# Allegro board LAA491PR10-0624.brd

Outline 230.4 x 191.1 mm; copper layers: TOP, GND1, IN1, VCC, IN2, IN3, GND2, BOTTOM. Coordinates in mm from the lower left corner of the outline.
Outline path: 0,56.85 10.3,56.85 arc(10.8,57.35) 10.3,57.85 10.3,69.35 arc(10.8,69.85) 10.3,70.35 0.8,70.35 0.8,74.66 13.2,74.66 arc(13.7,75.16) 13.2,75.66 13.2,89.94 arc(13.7,90.44) 13.2,90.94 0.6,90.94 0.6,95.91 1.69,95.91 arc(2.4,96.2) 2.69,96.91 2.69,99.5 4.3,99.5 arc(5.3,100.5) 4.3,101.5 4.3,114.5 arc(5.3,115.5) 4.3,116.5 2.69,116.5 2.69,120.4 23.65,120.4 arc(24.11,120.51) 24.46,120.83 arc(27.53,122.04) 29.86,119.7 arc(30.21,119.13) 30.84,118.9 37,118.9 arc(37.71,119.19) 38,119.9 38,120.4 48,120.4 arc(64.11,124.09) 77.01,134.43 arc(77.49,134.76) 78.07,134.77 arc(78.68,134.78) 79.17,135.14 arc(81.4,138.65) 83.23,142.37 arc(83.29,142.98) 82.98,143.51 arc(82.68,144.01) 82.71,144.59 arc(84.42,150.9) 85,157.4 85,159.8 89.93,159.8 89.93,153.52 arc(90.37,152.46) 91.43,152.02 118.73,152.02 arc(119.79,152.46) 120.23,153.52 120.23,159.8 124.5,159.8 arc(125.21,160.09) 125.5,160.8 125.5,190.1 133.8,190.1 arc(134.51,190.39) 134.8,191.1 160.3,191.1 arc(160.59,190.39) 161.3,190.1 198.4,190.1 198.4,182.1 arc(198.69,181.39) 199.4,181.1 202.2,181.1 202.2,180.6 arc(202.49,179.89) 203.2,179.6 225.2,179.6 arc(225.91,179.89) 226.2,180.6 226.2,181.1 230.4,181.1 230.4,0 165.4,0 165.4,7.48 arc(165.11,8.19) 164.4,8.48 89.4,8.48 89.4,11.48 arc(89.11,12.19) 88.4,12.48 62.4,12.48 arc(61.69,12.19) 61.4,11.48 61.4,8.98 56.4,8.98 arc(56.05,8.83) 55.9,8.48 49.9,8.48 arc(49.75,8.83) 49.4,8.98 47.4,8.98 arc(47.05,8.83) 46.9,8.48 40.9,8.48 arc(40.75,8.83) 40.4,8.98 38.4,8.98 arc(38.05,8.83) 37.9,8.48 31.9,8.48 arc(31.75,8.83) 31.4,8.98 27.8,8.98 arc(27.45,8.83) 27.3,8.48 26.84,5.22 arc(26.8,4.88) 26.77,4.55 arc(21.88,0) 17,4.57 arc(16.68,5.23) 16,5.5 0,5.5 0,8.92 12.66,8.92 arc(13.16,9.42) 12.66,9.92 12.66,15.75 arc(13.16,16.25) 12.66,16.75 0,16.75 0,21.6 7.47,21.6 arc(7.97,22.1) 7.47,22.6 7.47,34.2 arc(7.97,34.7) 7.47,35.2 0.8,35.2 0.8,39.25 10.3,39.25 arc(10.8,39.75) 10.3,40.25 10.3,51.75 arc(10.8,52.25) 10.3,52.75 0,52.75 0,56.85

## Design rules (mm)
net group CLK_: nets CLK_CPU_ITP CLK_CPU_ITP#
net group CSI: nets CSIN CSIP
net group DIFFPAIR2: nets I2C1_SCL_TCH_PAD I2C1_SDA_TCH_PAD
net group DIFFPAIR3: nets CSCL CSDA
net group DIFFPAIR5: nets EC_SMB_CK2 EC_SMB_DA2
net group DIFFPAIR9: nets CPU_EDP_AUX#_C CPU_EDP_AUX_C
net group DIFFPAIR13: nets PCSCL PCSDA
net group DIFFPAIR14: nets CRT_CLK_1 CRT_DATA_1
net group DIFFPAIR16: nets ISPSCL_R ISPSDA_R
net group DIFFPAIR17: nets DDI1_LANE_N0_C DDI1_LANE_P0_C
net group DIFFPAIR18: nets DDI1_LANE_N1_C DDI1_LANE_P1_C
net group DIFFPAIR19: nets CRT_CLK CRT_DATA
net group DIFFPAIR21: nets MDO2+ MDO2-
net group EDID_CLK: nets EDID_CLK EDID_DATA
net group MIIC_SCL: nets MIIC_SCL MIIC_SDA
net group PCIE_PRX_LANTX_P3_C: nets PCIE_PRX_LANTX_N3_C PCIE_PRX_LANTX_P3_C
net group PECI-SINGLE: nets PECI_EC PECI_KB9012
net group SENSE: nets VCCSENSE VSSSENSE
net group SMB-15: nets SML1_SMBCLK SML1_SMBDATA
net group VCIN0_PH: nets ECAGND VCIN0_PH
net group WCKA0_0: nets WCKA0_0 WCKA0B_0
net group WCKA0_1: nets WCKA0_1 WCKA0B_1
net group WCKA1_0: nets WCKA1_0 WCKA1B_0
net group WCKA1_1: nets WCKA1_1 WCKA1B_1
net group WCKB0_0: nets WCKB0_0 WCKB0B_0
net group WCKB0_1: nets WCKB0_1 WCKB0B_1
net group WCKB1_0: nets WCKB1_0 WCKB1B_0
net group WCKB1_1: nets WCKB1_1 WCKB1B_1
net group 12: nets PCH_OPI_COMP PCH_PCIE_RCOMP SATA_IREF
net group ASYNC: nets DDR3_DRAMRST# DDR3_DRAMRST#_CPU H_PROCHOT# H_PROCHOT#_R H_VCCST_PWRGD_XDP XDP_OBS0_R XDP_OBS1_R
net group AUDIO: nets PCH_AZ_BITCLK PCH_AZ_CODEC_BITCLK PCH_AZ_CODEC_RST# PCH_AZ_CODEC_SDIN0 PCH_AZ_CODEC_SDOUT PCH_AZ_CODEC_SYNC PCH_AZ_RST# PCH_AZ_SDOUT PCH_AZ_SYNC
net group CLK: nets SUSCLK
net group CLK-SINGLE: nets CLK_PCI_LPC
net group CR_LOW: nets DSWODVREN INTRUDER# PCH_DPWROK PCH_INTVRMEN PCH_RSMRST#_R SYS_PWROK SYS_PWROK_R SYS_RESET#
net group DDRA-ADD: nets DDR_A_BS0 DDR_A_BS1 DDR_A_BS2 DDR_A_CAS# DDR_A_MA0 DDR_A_MA1 DDR_A_MA2 DDR_A_MA3 DDR_A_MA4 DDR_A_MA5 DDR_A_MA6 DDR_A_MA7 DDR_A_MA8 DDR_A_MA9 DDR_A_MA10 DDR_A_MA11 DDR_A_MA12 DDR_A_MA13 DDR_A_MA14 DDR_A_MA15 DDR_A_RAS# DDR_A_WE#
net group DDRA-CTL: nets DDR_CKE0_DIMMA DDR_CKE1_DIMMA DDR_CS0_DIMMA# DDR_CS1_DIMMA# M_ODT0 M_ODT1
net group DDRA-D0: nets DDR_A_D0 DDR_A_D1 DDR_A_D2 DDR_A_D3 DDR_A_D4 DDR_A_D5 DDR_A_D6 DDR_A_D7
net group DDRA-D1: nets DDR_A_D8 DDR_A_D9 DDR_A_D10 DDR_A_D11 DDR_A_D12 DDR_A_D13 DDR_A_D14 DDR_A_D15 DDR_A_DQS1 DDR_A_DQS#1
net group DDRA-D2: nets DDR_A_D16 DDR_A_D17 DDR_A_D18 DDR_A_D19 DDR_A_D20 DDR_A_D21 DDR_A_D22 DDR_A_D23
net group DDRA-D3: nets DDR_A_D24 DDR_A_D25 DDR_A_D26 DDR_A_D27 DDR_A_D28 DDR_A_D29 DDR_A_D30 DDR_A_D31
net group DDRA-D4: nets DDR_A_D32 DDR_A_D33 DDR_A_D34 DDR_A_D35 DDR_A_D36 DDR_A_D37 DDR_A_D38 DDR_A_D39
net group DDRA-D5: nets DDR_A_D40 DDR_A_D41 DDR_A_D42 DDR_A_D43 DDR_A_D44 DDR_A_D45 DDR_A_D46 DDR_A_D47
net group DDRA-D6: nets DDR_A_D48 DDR_A_D49 DDR_A_D50 DDR_A_D51 DDR_A_D52 DDR_A_D53 DDR_A_D54 DDR_A_D55
net group DDRA-D7: nets DDR_A_D56 DDR_A_D57 DDR_A_D58 DDR_A_D59 DDR_A_D60 DDR_A_D61 DDR_A_D62 DDR_A_D63
net group DDRB-ADD: nets DDR_B_BS0 DDR_B_BS1 DDR_B_BS2 DDR_B_CAS# DDR_B_MA0 DDR_B_MA1 DDR_B_MA2 DDR_B_MA3 DDR_B_MA4 DDR_B_MA5 DDR_B_MA6 DDR_B_MA7 DDR_B_MA8 DDR_B_MA9 DDR_B_MA10 DDR_B_MA11 DDR_B_MA12 DDR_B_MA13 DDR_B_MA14 DDR_B_MA15 DDR_B_RAS# DDR_B_WE#
net group DDRB-CTL: nets DDR_CKE2_DIMMB DDR_CKE3_DIMMB DDR_CS2_DIMMB# DDR_CS3_DIMMB# M_ODT2 M_ODT3
net group DDRB-D0: nets DDR_B_D0 DDR_B_D1 DDR_B_D2 DDR_B_D3 DDR_B_D4 DDR_B_D5 DDR_B_D6 DDR_B_D7
net group DDRB-D1: nets DDR_B_D8 DDR_B_D9 DDR_B_D10 DDR_B_D11 DDR_B_D12 DDR_B_D13 DDR_B_D14 DDR_B_D15
net group DDRB-D2: nets DDR_B_D16 DDR_B_D17 DDR_B_D18 DDR_B_D19 DDR_B_D20 DDR_B_D21 DDR_B_D22 DDR_B_D23
net group DDRB-D3: nets DDR_B_D24 DDR_B_D25 DDR_B_D26 DDR_B_D27 DDR_B_D28 DDR_B_D29 DDR_B_D30 DDR_B_D31
net group DDRB-D4: nets DDR_B_D32 DDR_B_D33 DDR_B_D34 DDR_B_D35 DDR_B_D36 DDR_B_D37 DDR_B_D38 DDR_B_D39
net group DDRB-D5: nets DDR_B_D40 DDR_B_D41 DDR_B_D42 DDR_B_D43 DDR_B_D44 DDR_B_D45 DDR_B_D46 DDR_B_D47
net group DDRB-D6: nets DDR_B_D48 DDR_B_D49 DDR_B_D50 DDR_B_D51 DDR_B_D52 DDR_B_D53 DDR_B_D54 DDR_B_D55
net group DDRB-D7: nets DDR_B_D56 DDR_B_D57 DDR_B_D58 DDR_B_D59 DDR_B_D60 DDR_B_D61 DDR_B_D62 DDR_B_D63
net group DP: nets CPU_DPB_AUX CPU_DPB_AUX# CPU_DPB_AUX#_C CPU_DPB_AUX_C CPU_DPC_AUX CPU_DPC_AUX#
net group EDP: nets CPU_EDP_N0_C CPU_EDP_N1_C CPU_EDP_P0_C CPU_EDP_P1_C
net group HDA: nets AUD_HP_OUT_L_CN AUD_HP_OUT_R_CN HPOUT-L HPOUT-R MIC_IN MIC_IN_R RING2 RING2_R
net group HDMI: nets CPU_DPB_CTRLCLK CPU_DPB_CTRLDAT DDI1_LANE_N0 DDI1_LANE_N1 DDI1_LANE_P0 DDI1_LANE_P1
net group KB: nets KSI0 KSI1 KSI2 KSI3 KSI4 KSI5 KSI6 KSI7 KSO0 KSO1 KSO2 KSO3 KSO4 KSO5 KSO6 KSO7 KSO8 KSO9 KSO10 KSO11 KSO12 KSO13 KSO14 KSO15 KSO16
net group LPC: nets LPC_LAD0 LPC_LAD1 LPC_LAD2 LPC_LAD3 LPC_LFRAME#
net group LVDS: nets EDP_AUX EDP_AUX# EDP_N0 EDP_N1 EDP_P0 EDP_P1 LVDS_A0+ LVDS_A0- LVDS_A1+ LVDS_A1- LVDS_A2+ LVDS_A2- LVDS_ACLK+ LVDS_ACLK- LVDS_B0+ LVDS_B0- LVDS_B1+ LVDS_B1- LVDS_B2+ LVDS_B2- LVDS_BCLK+ LVDS_BCLK-
net group MDI: nets MDI0+ MDI0- MDI1+ MDI1- MDO0+ MDO0- MDO1+ MDO1- MDO3+ MDO3-
net group PCIE: nets PCIE_PRX_LANTX_N3 PCIE_PRX_LANTX_P3 PCIE_PTX_LANRX_N3 PCIE_PTX_LANRX_P3 PCIE_PTX_WLANRX_N4_C PCIE_PTX_WLANRX_P4_C
net group PEG: nets PEG_CTX_GRX_N0 PEG_CTX_GRX_N1 PEG_CTX_GRX_N2 PEG_CTX_GRX_N3 PEG_CTX_GRX_P0 PEG_CTX_GRX_P1 PEG_CTX_GRX_P2 PEG_CTX_GRX_P3
net group POWER: nets +0.675VS +0.675VSP +1.5VS +1.5VSP +1.5VSP_ON +1.35V +1.35VP +3V_WLAN +3VALW_PCH +3VALWP +3VLP +3VS_CAM +3VS_RT +5V_HDD +5V_PVDD +5V_USB_PWR1 +5V_USB_PWR2 +5V_USB_PWR3 +5V_USB_PWR4 +5VA +5VALWP +5VS_ODD +5VS_TOUCH +AVCC33 +DIMM1_VREF_DQ +DIMM2_VREF_DQ +DVCC33 +EC_VCCA +FAN_POWER +INV_PWR_SRC +LAN_IO +LAN_VDD +LCDVDD +MIC2-VREFO +PCH_VCCDSW +PCH_VCCDSW_R +RTCBATT +RTCVCC +SM_VREF_CA +SM_VREF_CA_DIMM +SM_VREF_DQ0 +SM_VREF_DQ0_DIMM1 +SM_VREF_DQ1 +SM_VREF_DQ1_DIMM2 +SW_LX +SWR_V12 +V18R +VCC_3IN1 +VCC_PWR_SRC +VCCIO_OUT +VCCIOA_OUT +VCHGR
net group RCOMP: nets SM_RCOMP0 SM_RCOMP1 SM_RCOMP2
net group RTC: nets PCH_RTCRST# PCH_RTCX1 PCH_RTCX2 SRTCRST#
net group SATA: nets SATA_PRX_DTX_N0 SATA_PRX_DTX_N0_C SATA_PRX_DTX_N1 SATA_PRX_DTX_P0 SATA_PRX_DTX_P0_C SATA_PRX_DTX_P1 SATA_PTX_DRX_N0 SATA_PTX_DRX_N1 SATA_PTX_DRX_P0 SATA_PTX_DRX_P1
net group SMB_10: nets DDR_XDP_SMBCLK_R1 DDR_XDP_SMBDAT_R1 SML0CLK SML0DATA
net group SPI: nets PCH_SPI_CLK PCH_SPI_CLK_R PCH_SPI_CS0# PCH_SPI_HOLD1# PCH_SPI_HOLD# PCH_SPI_MISO PCH_SPI_MISO_1 PCH_SPI_MOSI PCH_SPI_MOSI_1 PCH_SPI_WP1# PCH_SPI_WP#
net group SPK: nets INT-SPK-L+ INT-SPK-L- INT-SPK-R+ INT-SPK-R-
net group SVID: nets H_CPU_SVIDALRT# H_CPU_SVIDCLK H_CPU_SVIDDATA VR_SVID_ALRT# VR_SVID_CLK VR_SVID_DAT
net group THERMTRIP-SINGLE: nets H_THERMTRIP#
net group USB20: nets USB20_CAM_N7_R USB20_CAM_P7_R USB20_CR_N6_R USB20_CR_P6_R USB20_JUSB3_N2 USB20_JUSB3_N2_R USB20_JUSB3_P2 USB20_JUSB3_P2_R USB20_USBDB_N3_R USB20_USBDB_P3_R
net group USB30: nets USB3RN1_JUSB2 USB3RN1_JUSB2_R USB3RN2_JUSB1 USB3RN2_JUSB1_R USB3RP1_JUSB2 USB3RP1_JUSB2_R USB3RP2_JUSB1 USB3RP2_JUSB1_R USB3TN1_JUSB2_C USB3TN1_JUSB2_R USB3TN2_JUSB1_C USB3TN2_JUSB1_R USB3TP1_JUSB2_C USB3TP1_JUSB2_R USB3TP2_JUSB1_C USB3TP2_JUSB1_R
net group VRAMA1-D0: nets DDBIA1_0 DQA1_0 DQA1_1 DQA1_2 DQA1_3 DQA1_4 DQA1_5 DQA1_6 DQA1_7 EDCA1_0
net group VRAMA1-D1: nets DDBIA1_1 DQA1_8 DQA1_9 DQA1_10 DQA1_11 DQA1_12 DQA1_13 DQA1_14 DQA1_15 EDCA1_1
net group VRAMA1-D2: nets DDBIA1_2 DQA1_16 DQA1_17 DQA1_18 DQA1_19 DQA1_20 DQA1_21 DQA1_22 DQA1_23 EDCA1_2
net group VRAMA1-D3: nets DDBIA1_3 DQA1_24 DQA1_25 DQA1_26 DQA1_27 DQA1_28 DQA1_29 DQA1_30 DQA1_31 EDCA1_3
net group VRAMA-ADD: nets ADBIA0 ADBIA1 CASA0# CASA1# CKEA0 CKEA1 CSA0#_0 CSA1#_0 MAA0_0 MAA0_1 MAA0_2 MAA0_3 MAA0_4 MAA0_5 MAA0_6 MAA0_7 MAA0_8 MAA1_0 MAA1_1 MAA1_2 MAA1_3 MAA1_4 MAA1_5 MAA1_6 MAA1_7 MAA1_8 RASA0# RASA1# WEA0# WEA1#
net group VRAMA-D0: nets DDBIA0_0 DQA0_0 DQA0_1 DQA0_2 DQA0_3 DQA0_4 DQA0_5 DQA0_6 DQA0_7 EDCA0_0
net group VRAMA-D1: nets DDBIA0_1 DQA0_8 DQA0_9 DQA0_10 DQA0_11 DQA0_12 DQA0_13 DQA0_14 DQA0_15 EDCA0_1
net group VRAMA-D2: nets DDBIA0_2 DQA0_16 DQA0_17 DQA0_18 DQA0_19 DQA0_20 DQA0_21 DQA0_22 DQA0_23 EDCA0_2
net group VRAMA-D3: nets DDBIA0_3 DQA0_24 DQA0_25 DQA0_26 DQA0_27 DQA0_28 DQA0_29 DQA0_30 DQA0_31 EDCA0_3
net group VRAMB0-D0: nets DDBIB0_0 DQB0_0 DQB0_1 DQB0_2 DQB0_3 DQB0_4 DQB0_5 DQB0_6 DQB0_7 EDCB0_0
net group VRAMB0-D1: nets DDBIB0_1 DQB0_8 DQB0_9 DQB0_10 DQB0_11 DQB0_12 DQB0_13 DQB0_14 DQB0_15 EDCB0_1
net group VRAMB0-D2: nets DDBIB0_2 DQB0_16 DQB0_17 DQB0_18 DQB0_19 DQB0_20 DQB0_21 DQB0_22 DQB0_23 EDCB0_2
net group VRAMB0-D3: nets DDBIB0_3 DQB0_24 DQB0_25 DQB0_26 DQB0_27 DQB0_28 DQB0_29 DQB0_30 DQB0_31 EDCB0_3
net group VRAMB1-D0: nets DDBIB1_0 DQB1_0 DQB1_1 DQB1_2 DQB1_3 DQB1_4 DQB1_5 DQB1_6 DQB1_7 EDCB1_0
net group VRAMB1-D1: nets DDBIB1_1 DQB1_8 DQB1_9 DQB1_10 DQB1_11 DQB1_12 DQB1_13 DQB1_14 DQB1_15 EDCB1_1
net group VRAMB1-D2: nets DDBIB1_2 DQB1_16 DQB1_17 DQB1_18 DQB1_19 DQB1_20 DQB1_21 DQB1_22 DQB1_23 EDCB1_2
net group VRAMB1-D3: nets DDBIB1_3 DQB1_24 DQB1_25 DQB1_26 DQB1_27 DQB1_28 DQB1_29 DQB1_30 DQB1_31 EDCB1_3
net group VRAMB-ADD: nets ADBIB0 ADBIB1 CASB0# CASB1# CKEB0 CKEB1 CSB0#_0 CSB1#_0 DRAM_RST# DRAM_RST#_R MAB0_0 MAB0_1 MAB0_2 MAB0_3 MAB0_4 MAB0_5 MAB0_6 MAB0_7 MAB0_8 MAB1_0 MAB1_1 MAB1_2 MAB1_3 MAB1_4 MAB1_5 MAB1_6 MAB1_7 MAB1_8 RASB0# RASB1# WEB0# WEB1#
nets with their own width: min track width 0.254; nets +1.8VSP +3VALW +VGA_CORE +VGA_PCIEP CLK_BIASREF
nets with their own width: min track width 0.508; nets +1.2VSP_B+ +1.05V_PGOOD +1.05VS_APLLOPI +1.05VS_ASATA3PLL +1.05VS_AUSB3PLL +1.05VS_AXCK_DCB +1.05VS_AXCK_LCPLL +1.05VSP +1.8VGS +1.8VS +1.8VSP_ON +1.35V_MEM_GFX +1.35VGPUP +1.35VS_VGA +3VALW_PCH_GATE +3VGS +3VS +5VALW +5VS +AVDD +BIF_VDDC +CHGRTC +CPU_CORE +DPAB_VDD10 +DPAB_VDD18 +DPCD_VDD10 +DPCD_VDD18 +DPEF_VDD10 +DPEF_VDD18 +DPLL_PVDD +DPLL_VDDC +LCDVDD_CONN +MPV18 +PCIE_PVDD +PCIE_VDDR +SPV10 +SPV18 +TSVDD +VCCIO_OUT_R +VCCRTCEXT +VDD1DI +VDD_MEM15_REFDA +VDD_MEM15_REFDB +VDD_MEM15_REFSA +VDD_MEM15_REFSB +VDDC_CT +VDDCI +VDDCIP +VDDR4 +VREFG_GPU EDP_COMP GND GNDA
nets with their own width: min track width 1.27; nets +1.05VS

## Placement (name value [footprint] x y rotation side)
C1  -  [C_0402]  9.62 110.41 90 bottom
C2  -  [C_0402]  11.33 100.76 90 bottom
C3  -  [C_0402]  11.33 104.38 90 bottom
C4  -  [C_0402]  11.33 107.14 270 bottom
C5  -  [C_0402]  10.13 100.76 90 bottom
C6  -  [C_0402]  10.06 104.38 90 bottom
C7  -  [C_0402]  10.06 107.14 270 bottom
C8  -  [C_0402]  8.59 113.41 0 top
C9  -  [C_0402]  12.35 113.23 270 top
C10  -  [C_0402]  12.35 109.17 270 top
C11  -  [C_0402]  10.7 113.33 90 top
C12  -  [C_0402]  14.25 114.03 90 top
C13  -  [C_0402]  15.14 114.03 90 top
C20  -  [C_0603]  19.33 109.15 180 top
C21  -  [C_0402]  24.22 97.61 270 bottom
C22  -  [C_0402]  17.17 97.74 270 bottom
C23  -  [C_0402]  15.35 101.98 180 top
C24  -  [C_0402]  15.35 104.9 180 top
C25  -  [C_0402]  15.35 103.38 180 top
C26  -  [C_0402]  15.35 106.38 180 top
C27  -  [C_0603]  24.92 108.84 90 top
C28  -  [C_0402]  19.83 97.74 270 bottom
C29  -  [C_0402]  17.43 108.76 90 bottom
C30  -  [C_0402]  22.89 97.61 270 bottom
C31  -  [C_0402]  18.32 108.76 90 bottom
C32  -  [C_0402]  27.96 103.82 0 bottom
C33  -  [C_0402]  27.96 102.93 0 bottom
C34  -  [C_0402]  29.92 102.55 0 bottom
C35  -  [C_0402]  107.79 96.92 270 bottom
C36  -  [C_0402]  105.63 96.92 270 bottom
C37  -  [C_0402]  103.47 96.92 270 bottom
C38  -  [C_0402]  101.31 96.92 270 bottom
C39  -  [C_0603]  108.87 97.17 270 bottom
C40  -  [C_0603]  101.92 112.61 270 top
C41  -  [C_0603]  106.71 97.1 270 bottom
C42  -  [C_0603]  104.55 97.1 270 bottom
C43  -  [C_0603]  103.69 112.61 270 top
C44  -  [C_0603]  132.32 137.13 270 top
C45  -  [C_0603]  102.39 97.1 270 bottom
C46  -  [C_0402]  22.03 97.61 270 bottom
C47  -  [C_0402]  21.49 108.76 90 bottom
C48  -  [C_0402]  26.7 103.57 270 top
C49  -  [C_0402]  29.92 101.66 0 bottom
C50  -  [C_0402]  123.22 118.32 270 top
C51  -  [C_0402]  149.29 105.73 0 top
C52  -  [C_0402]  124.68 111.95 90 top
C53  -  [C_0402]  124.55 119.68 180 top
C54  -  [C_0402]  134.08 97.3 270 bottom
C55  -  [C_0402]  134.97 97.3 270 bottom
C56  -  [C_0402]  135.86 97.3 270 bottom
C57  -  [C_0402]  130.34 121.04 180 top
C58  -  [C_0402]  120.48 131.46 0 bottom
C59  -  [C_1206]  119.66 134.19 0 bottom
C60  -  [C_0603]  131.03 122.63 90 top
C61  -  [C_0402]  122.79 119.71 180 top
C62  -  [C_0402]  129.95 123.06 90 top
C63  -  [C_0402]  125.31 130.62 90 bottom
C64  -  [C_0402]  118.33 96.42 270 top
C65  -  [C_1206]  125.44 134.06 0 bottom
C66  -  [C_0603]  119.73 94.43 180 top
C67  -  [C_0402]  119.99 111.07 180 top
C68  -  [C_0402]  123.85 114.64 270 top
C69  -  [C_0402]  118.9 114.51 270 top
C70  -  [C_1206]  125.3 136.26 0 bottom
C71  -  [C_0402]  121.7 118.39 270 top
C72  -  [C_0603]  100.23 97.1 270 bottom
C73  -  [C_0402]  122.72 116.02 180 top
C74  -  [C_0603]  99.03 97.1 270 bottom
C75  -  [C_0402]  117.43 110.75 90 top
C76  -  [C_0402]  120.29 112.66 0 top
C77  -  [C_0402]  121.63 110.17 90 top
C78  -  [C_0603]  122.9 113.74 180 top
C79  -  [C_0402]  27.14 99.13 270 bottom
C80  -  [C_0402]  23.27 108.76 90 bottom
C81  -  [C_0402]  124.46 109.75 270 top
C82  -  [C_0603]  122.9 114.95 180 top
C83  -  [C_0402]  119.6 119.97 270 top
C84  -  [C_1206]  121.3 136.66 0 bottom
C85  -  [C_0402]  119.61 131.46 180 bottom
C86  -  [C_1206]  118.2 134.19 180 bottom
C87  -  [C_0402]  120.3 113.54 90 top
C88  -  [C_0402]  117.5 117.37 270 top
C89  -  [C_0402]  15.35 101.98 180 bottom
C90  -  [C_0402]  18.06 96.82 90 bottom
C91  -  [C_0402]  27.13 100.26 0 bottom
C92  -  [C_0402]  20.72 97.74 270 bottom
C93  -  [C_0603]  23.65 108.84 90 top
C94  -  [C_0402]  22.38 108.76 90 bottom
C95  -  [C_0402]  91.71 124.58 0 top
C96  -  [C_0402]  92.26 120.11 0 top
C411  -  [C_0402]  23.14 115.81 90 bottom
C2305  -  [C_0603]  99.53 29.03 0 bottom
C2306  -  [C_0603]  99.53 27.82 0 bottom
C2307  -  [C_0805]  102.58 30.96 270 bottom
C2308  -  [C_0603]  104.04 31.06 270 bottom
C2309  -  [C_0603]  95.72 26.49 270 top
C2310  -  [C_0805]  142.31 27.51 0 top
C2311  -  [C_0603]  138.33 21.79 90 top
C2312  -  [C_0603]  142.21 29.03 0 top
C2313  -  [C_0603]  139.54 21.79 90 top
C2314  -  [C_0603]  142.21 20.74 90 bottom
C2316  -  [C_0603]  93.5 27.82 180 bottom
C2318  -  [C_0603]  93.5 29.03 180 bottom
C2322  -  [C_0603]  94.52 26.49 270 top
C2323  -  [C_0603]  89.69 30.74 270 bottom
C2324  -  [C_0603]  90.9 30.74 270 bottom
C2326  -  [C_0402]  142.55 114.97 180 bottom
C2327  -  [C_0402]  159.36 85.48 90 bottom
C5212  -  [C_0402]  83.2 117.8 0 bottom
CA1  -  [C_0603]  28.54 25.92 90 bottom
CA2  -  [C_0603]  27.33 25.92 90 bottom
CA21  -  [C_0402]  34.43 20.2 0 top
CA22  -  [C_0402]  34.43 19.25 0 top
CA23  -  [C_0603]  20.41 22.11 0 bottom
CA24  -  [C_0402]  22.46 17.98 180 top
CA25  -  [C_0402]  21.1 19 0 top
CA29  -  [C_0402]  65.5 24.76 90 top
CA30  -  [C_0402]  65.5 23.9 270 top
CA31  -  [C_0402]  66.45 21.71 90 top
CA32  -  [C_0402]  66.45 20.85 270 top
CA33  -  [C_0402]  20.1 12.57 90 top
CA38  -  [C_0402]  15.98 19.12 180 top
CA39  -  [C_0402]  20.1 11.64 270 top
CA40  -  [C_0402]  17.05 19.09 0 top
CA51  -  [C_0402]  21.94 23.68 90 top
CA53  -  [C_0603]  27.91 17.47 90 bottom
CA54  -  [C_0402]  26.83 17.46 90 bottom
CA55  -  [C_0603]  31.33 13.98 0 top
CA56  -  [C_0402]  31.26 15.06 0 top
CA57  -  [C_0603]  32.1 16.9 0 top
CA58  -  [C_0402]  32.08 17.98 0 top
CA59  -  [C_0603]  32.22 23.44 0 top
CA60  -  [C_0402]  32.15 22.36 0 top
CA61  -  [C_0603]  23.75 15.96 270 top
CA62  -  [C_0603]  20.41 23.31 0 bottom
CA63  -  [C_0603]  23.75 14.56 90 bottom
CA64  -  [C_0603]  35.78 21.28 180 top
CA65  -  [C_0402]  32.15 24.52 0 top
CA67  -  [C_0603]  24.98 25.6 90 top
CA68  -  [C_0603]  26.19 25.6 90 top
CA69  -  [C_0402]  33.06 25.41 180 top
CA71  -  [C_0603]  20.86 23.76 90 top
CA74  -  [C_0603]  27.4 25.92 90 top
CC1  -  [C_0402]  146 99.13 0 bottom
CC2  -  [C_0402]  148.7 99.13 180 bottom
CC3  -  [C_0402]  129.49 95.58 0 top
CC4  -  [C_0402]  133.96 95.51 180 top
CC5  -  [C_0402]  127.21 95.26 0 bottom
CC6  -  [C_0402]  118.92 134.46 180 top
CC7  -  [C_0402]  114.45 134.46 0 top
CC8  -  [C_0402]  97.05 95.53 0 bottom
CC9  -  [C_0402]  94.41 95.53 180 bottom
CC10  -  [C_0402]  96.19 95.53 180 bottom
CC11  -  [C_0402]  149.5 103.39 0 top
CC13  -  [C_0402]  70.27 108.34 90 bottom
CC14  -  [C_0402]  61.95 97.74 180 top
CC15  -  [C_0402]  62.03 94.13 180 top
CC16  -  [C_0402]  61.89 88.68 270 bottom
CC17  -  [C_0402]  61.89 101.36 90 bottom
CC18  -  [C_0402]  158.88 117.94 0 bottom
CC19  -  [C_0402]  158.88 117.05 0 bottom
CC20  -  [C_0402]  160.66 119.46 0 bottom
CC21  -  [C_0402]  160.66 118.57 0 bottom
CC22  -  [C_0402]  158.88 120.73 0 bottom
CC23  -  [C_0402]  158.88 119.84 0 bottom
CC24  -  [C_0402]  160.66 122.51 0 bottom
CC25  -  [C_0402]  160.66 121.62 0 bottom
CC26  -  [C_0603]  136.94 97.29 270 bottom
CC27  -  [C_0402]  86.85 128.22 90 bottom
CC28  -  [C_0402]  79.02 122.5 90 bottom
CC29  -  [C_0402]  71.16 108.34 90 bottom
CC30  -  [C_0402]  63.2 106.35 180 bottom
CC31  -  [C_0402]  61.37 89.29 270 top
CC32  -  [C_0402]  39.91 100.01 90 bottom
CC33  -  [C_0402]  150.54 107.34 0 top
CC34  -  [C_0402]  133.44 112.72 0 top
CC35  -  [C_0402]  50.4 62.52 180 top
CC40  -  [C_0402]  39.02 100.01 90 bottom
CD1  -  [C_0402]  42.63 71.83 0 top
CD2  -  [C_0402]  42.63 72.72 0 top
CD3  -  [C_0402]  51.27 62.55 90 top
CD4  -  [C_0402]  73.88 62.48 90 top
CD5  -  [C_0402]  68.99 63.05 90 top
CD6  -  [C_0402]  66.7 63.4 270 top
CD7  -  [C_0402]  65.37 72.01 90 top
CD8  -  [C_0402]  69.94 70.67 90 top
CD9  -  [C_0402]  77.5 62.48 90 top
CD10  -  [C_0402]  76.7 70.69 90 top
CD11  -  [C_0402]  73.63 70.67 90 top
CD12  -  [C_0603]  75.72 62.56 90 top
CD13  -  [C_0603]  75.47 70.69 90 top
CD14  -  [C_0603]  82.68 70.76 90 top
CD15  -  [C_D2]  73.27 76.02 180 top
CD16  -  [C_0603]  67.91 62.56 90 top
CD17  -  [C_0603]  72.1 62.56 90 top
CD18  -  [C_0603]  79.34 62.56 90 top
CD19  -  [C_0603]  66.51 71.77 90 top
CD20  -  [C_0603]  71.78 70.69 90 top
CD21  -  [C_0402]  81.69 62.55 90 top
CD22  -  [C_0402]  82.58 62.55 90 top
CD23  -  [C_0402]  47.51 67.36 0 top
CD24  -  [C_0402]  105.26 70.75 180 top
CD25  -  [C_0402]  105.26 71.64 180 top
CD26  -  [C_0402]  105.01 62.94 180 top
CD27  -  [C_0402]  104.94 63.83 180 top
CD28  -  [C_0603]  105.29 64.91 180 top
CD29  -  [C_0603]  105.25 72.72 180 top
CD30  -  [C_0402]  102.58 70.74 90 top
CD31  -  [C_0402]  103.47 70.74 90 top
CD32  -  [C_0402]  120.41 73.42 0 top
CD33  -  [C_0402]  120.41 72.53 0 top
CD34  -  [C_0402]  129.32 62.55 90 top
CD35  -  [C_0402]  152.49 62.55 90 top
CD36  -  [C_0402]  148.87 62.55 90 top
CD37  -  [C_0402]  145.25 62.55 90 top
CD38  -  [C_0402]  156.05 62.48 90 top
CD39  -  [C_0402]  155.73 70.74 90 top
CD40  -  [C_0402]  152.18 70.74 90 top
CD41  -  [C_0402]  148.56 70.74 90 top
CD42  -  [C_0402]  144.94 70.74 90 top
CD43  -  [C_0603]  150.65 62.56 90 top
CD44  -  [C_0603]  147.03 62.56 90 top
CD45  -  [C_0603]  154.27 62.56 90 top
CD46  -  [C_0603]  146.78 70.75 90 top
CD47  -  [C_0603]  150.33 70.75 90 top
CD48  -  [C_0603]  153.95 70.75 90 top
CD49  -  [C_0603]  157.57 70.75 90 top
CD50  -  [C_0603]  157.89 62.56 90 top
CD51  -  [C_D2]  152.68 82.98 0 top
CD52  -  [C_0402]  160.3 62.55 90 top
CD53  -  [C_0402]  161.19 62.55 90 top
CD54  -  [C_0402]  183.62 72.27 180 top
CD55  -  [C_0402]  183.62 73.16 180 top
CD56  -  [C_0402]  183.56 62.56 180 top
CD57  -  [C_0402]  183.56 63.45 180 top
CD58  -  [C_0603]  183.83 64.53 180 top
CD59  -  [C_0603]  183.54 74.24 180 top
CD60  -  [C_0402]  180.94 72.26 90 top
CD61  -  [C_0402]  181.83 72.26 90 top
CD62  -  [C_0603]  101.5 70.58 90 top
CD63  -  [C_0402]  53.03 17.56 270 top
CD64  -  [C_0402]  44.9 62.98 270 top
CE1  -  [C_0402]  199.41 36.9 0 top
CE2  -  [C_0402]  191.55 33.74 270 top
CE5  -  [C_0402]  178.52 37.54 0 top
CE6  -  [C_0402]  185.49 32.93 90 top
CE7  -  [C_0402]  200.61 34.49 0 top
CE8  -  [C_0402]  196.31 53.78 90 top
CE9  -  [C_0402]  199.94 49.73 180 top
CE11  -  [C_0402]  199.47 39.82 0 top
CE12  -  [C_0402]  187.41 31.82 0 top
CE15  -  [C_0402]  178.08 55.31 90 top
CE16  -  [C_0805]  179.32 39 180 top
CE18  -  [C_0402]  178.58 44.84 0 top
CE19  -  [C_0402]  179.48 55.31 90 top
CE20  -  [C_0402]  195.55 30.8 90 top
CE22  -  [C_0603]  48.73 106.06 180 bottom
CE23  -  [C_0402]  48.81 104.98 180 bottom
CE24  -  [C_0402]  50.05 106.12 0 bottom
CE25  -  [C_0603]  44.73 102.31 270 bottom
CE26  -  [C_0402]  183.61 53.34 90 top
CE27  -  [C_0402]  184.62 33.84 270 top
CE28  -  [C_0402]  188.31 33.61 270 top
CE29  -  [C_0402]  193.96 33.74 270 top
CE30  -  [C_0402]  175.87 44.65 180 top
CE31  -  [C_0402]  196.85 33.81 270 top
CE32  -  [C_0402]  173.36 49.97 180 top
CE33  -  [C_0402]  182.2 33.77 0 top
CE34  -  [C_0402]  172.84 42.92 90 top
CE35  -  [C_0402]  170.16 46.94 0 top
CE36  -  [C_0402]  192.89 43.13 0 bottom
CG1  -  [C_0402]  71.83 44.7 90 top
CG2  -  [C_0402]  71.15 39.01 270 top
CG3  -  [C_0402]  75.14 41.6 0 top
CG4  -  [C_0402]  68.94 43.38 180 top
CG5  -  [C_0805]  73.56 44.44 90 top
CG6  -  [C_0603]  69.8 44.46 90 top
CG7  -  [C_0402]  73.94 38.1 90 top
CG8  -  [C_0402]  68.81 39.82 180 top
CG9  -  [C_0402]  68.81 41.09 180 top
CG10  -  [C_0402]  70.23 39 270 top
CG11  -  [C_0402]  70.95 46.47 90 top
CI1  -  [C_APXK6R3ARA221MF451]  23.01 64.34 0 bottom
CI2  -  [C_0402]  19.21 63.97 270 bottom
CI3  -  [C_0402]  23.33 60.41 270 bottom
CI4  -  [C_0402]  24.22 60.41 270 bottom
CI6  -  [C_0805]  30.29 52.78 0 top
CI7  -  [C_0402]  31.2 54.11 0 top
CI8  -  [C_APXK6R3ARA221MF451]  23.58 52.72 0 bottom
CI9  -  [C_0402]  18.44 53.21 90 bottom
CI10  -  [C_0402]  23.7 47.88 0 bottom
CI11  -  [C_0402]  23.7 48.78 0 bottom
CI12  -  [C_0805]  27.04 61.48 0 top
CI13  -  [C_0402]  25.81 64.69 180 top
CI14  -  [C_0402]  28.01 64.53 0 top
CI15  -  [C_0402]  20.51 64.63 0 top
CI16  -  [C_0402]  22.56 34.74 0 top
CI17  -  [C_0402]  23.7 55.26 0 top
CI18  -  [C_0805]  27.03 59.66 0 top
CI19  -  [C_0402]  15.4 32.51 90 bottom
CI20  -  [C_APXK6R3ARA221MF451]  21.8 31.51 0 bottom
CI21  -  [C_0805]  27.04 63.19 0 top
CI22  -  [C_0402]  23.45 30.36 0 top
CI23  -  [C_0805]  22.74 31.7 0 top
CI24  -  [C_0402]  16.36 34.17 180 top
CI25  -  [C_0402]  209.07 41.46 90 top
CI26  -  [C_0402]  31.2 55 0 top
CI27  -  [C_0805]  22.74 33.41 0 top
CI30  -  [C_0402]  208.23 40.52 0 top
CI31  -  [C_0805]  208.35 39.19 0 top
CI32  -  [C_0402]  209.07 44.16 270 top
CI40  -  [C_0603]  20.29 64.53 270 bottom
CI43  -  [C_0603]  17.36 53.1 90 bottom
CI44  -  [C_0603]  14.32 32.33 90 bottom
CL15  -  [C_0402]  34.2 80.27 180 bottom
CL19  -  [C_0402]  36.6 88.25 90 bottom
CL20  -  [C_0402]  35.97 80.29 270 bottom
CL22  -  [C_0402]  35.26 83.56 0 top
CL26  -  [C_0402]  35.32 86.49 0 top
CL30  -  [C_0402]  42.07 88.16 270 bottom
CL31  -  [C_0402]  42.96 88.16 270 bottom
CL33  -  [C_1206]  22.95 79.25 270 top
CL34  -  [C_0402]  40.17 84.14 180 top
CL35  -  [C_0402]  40.17 85.15 180 top
CL36  -  [C_0402]  37.24 80.41 270 bottom
CL37  -  [C_0402]  38.57 79.44 90 bottom
CL38  -  [C_0603]  47.32 85.16 0 bottom
CL39  -  [C_0402]  43.78 80.46 180 bottom
CL41  -  [C_0402]  32.55 89.66 180 bottom
CL42  -  [C_0402]  40.17 83.12 180 top
CL43  -  [C_0603]  36.54 88.52 0 top
CL44  -  [C_0603]  35.02 80.77 270 top
CM40  -  [C_0402]  94.31 146.19 0 top
CM43  -  [C_0603]  112.68 148.32 0 top
CM44  -  [C_0402]  109.33 147.72 90 top
CM45  -  [C_0603]  100.8 143.89 270 top
CM46  -  [C_0402]  116.87 147.7 90 top
CM47  -  [C_0402]  105.69 147.76 90 top
CM48  -  [C_0402]  111.73 147.74 90 top
CM49  -  [C_0402]  108.45 147.72 90 top
CMOS1  -  [SHORTPADS]  113.18 40.16 0 bottom
CR1  -  [C_0402]  177.98 18.06 270 top
CR2  -  [C_0603]  179.06 17.98 270 top
CR3  -  [C_0402]  180.14 17.14 90 top
CR4  -  [C_0402]  172.42 22.17 0 top
CR5  -  [C_0402]  181.79 21.83 180 top
CR6  -  [C_0402]  177.32 28.03 270 top
CR7  -  [C_0402]  182.26 28.59 0 top
CR8  -  [C_0603]  189.26 29.16 270 top
CR9  -  [C_0402]  179.58 27.12 90 top
CR10  -  [C_0402]  181.77 23.61 270 top
CR11  -  [C_0402]  175.16 26.99 90 top
CRTF1  -  [F_1812]  12.09 112.33 270 bottom
CS5  -  [C_0402]  220.76 63.17 90 top
CS6  -  [C_0402]  219.87 63.17 90 top
CS7  -  [C_0805]  218.86 62.08 180 top
CS8  -  [C_0402]  222.64 100.36 180 bottom
CS9  -  [C_0402]  222.64 101.25 180 bottom
CS10  -  [C_0402]  223.18 113.48 180 bottom
CS11  -  [C_0402]  223.18 112.6 180 bottom
CS12  -  [C_0805]  223 111.2 180 bottom
CS13  -  [C_0402]  219.5 118.18 180 bottom
CS14  -  [C_0402]  222.64 103.5 180 bottom
CS15  -  [C_0402]  222.64 104.39 180 bottom
CS16  -  [C_0603]  221.83 122.68 0 bottom
CS17  -  [C_0402]  222.93 105.47 180 bottom
CS105  -  [C_0402]  224.39 38.36 180 top
CS106  -  [C_0402]  224.39 39.25 180 top
CS108  -  [C_0402]  224.39 41.03 180 top
CS109  -  [C_0402]  224.39 40.14 180 top
CV1  -  [C_0603]  196.63 156.54 90 top
CV3  -  [C_0603]  195.42 156.54 90 top
CV4  -  [C_0603]  218.53 122.37 0 top
CV5  -  [C_0603]  218.53 123.58 0 top
CV6  -  [C_0603]  218.02 102.12 270 top
CV7  -  [C_0603]  216.82 102.12 270 top
CV8  -  [C_0402]  164.43 156.21 90 top
CV9  -  [C_0402]  163.54 156.21 90 top
CV10  -  [C_0402]  194.85 156.14 90 bottom
CV11  -  [C_0402]  193.13 156.33 90 top
CV12  -  [C_0402]  219.03 131.96 0 top
CV13  -  [C_0402]  218.52 141.3 0 bottom
CV14  -  [C_0402]  165.89 156.21 90 bottom
CV15  -  [C_0402]  164.81 156.21 90 bottom
CV16  -  [C_0402]  163.92 156.21 90 bottom
CV17  -  [C_0402]  173.7 156.53 90 bottom
CV18  -  [C_0402]  219.49 143.09 270 bottom
CV19  -  [C_0402]  218.46 127.33 0 bottom
CV20  -  [C_0402]  218.46 125.55 0 bottom
CV21  -  [C_0402]  200.5 131.01 0 bottom
CV22  -  [C_0402]  201.41 132.79 180 bottom
CV23  -  [C_0402]  218.71 125.55 0 top
CV24  -  [C_0402]  219.62 127.33 180 top
CV25  -  [C_0402]  205.52 142.62 90 top
CV26  -  [C_0402]  203.74 143.53 270 top
CV27  -  [C_0402]  201.46 130.97 180 top
CV28  -  [C_0402]  200.55 128.34 0 top
CV29  -  [C_0402]  212.64 101.17 180 bottom
CV30  -  [C_0402]  211.73 99.39 0 bottom
CV31  -  [C_0402]  205.26 101.81 270 bottom
CV32  -  [C_0402]  203.48 100.9 90 bottom
CV33  -  [C_0402]  201.22 112.77 180 top
CV34  -  [C_0402]  200.31 114.55 0 top
CV35  -  [C_0402]  213.64 100.1 270 top
CV36  -  [C_0402]  211.87 99.18 90 top
CV37  -  [C_0402]  218.46 119.2 0 top
CV38  -  [C_0402]  218.46 117.42 0 top
CV39  -  [C_0402]  201.22 112.77 180 bottom
CV40  -  [C_0402]  200.31 114.55 0 bottom
CV41  -  [C_0603]  167.01 156.28 90 bottom
CV42  -  [C_0603]  162.78 156.16 90 bottom
CV43  -  [C_0402]  159.08 117.61 0 top
CV44  -  [C_0402]  159.08 116.72 0 top
CV45  -  [C_0402]  160.92 118.76 0 top
CV46  -  [C_0402]  160.92 117.87 0 top
CV47  -  [C_0402]  159.08 119.95 0 top
CV48  -  [C_0402]  159.08 119.07 0 top
CV49  -  [C_0402]  160.92 120.22 0 top
CV50  -  [C_0402]  160.92 121.11 0 top
CV59  -  [C_0402]  173.7 156.53 90 top
CV60  -  [C_0402]  172.81 156.53 90 top
CV61  -  [C_0402]  170.97 156.21 90 top
CV62  -  [C_0402]  188.69 156.27 90 top
CV63  -  [C_0402]  189.32 156.14 90 bottom
CV64  -  [C_0402]  186.91 156.27 90 top
CV65  -  [C_0402]  187.93 156.14 90 bottom
CV66  -  [C_0402]  185.96 156.27 90 top
CV67  -  [C_0402]  187.04 156.14 90 bottom
CV68  -  [C_0402]  185.07 156.27 90 top
CV69  -  [C_0402]  170.08 156.21 90 top
CV70  -  [C_0402]  169.07 156.21 90 top
CV71  -  [C_0402]  168.18 156.21 90 top
CV72  -  [C_0402]  166.78 156.21 90 top
CV73  -  [C_0402]  165.89 156.21 90 top
CV74  -  [C_0402]  186.15 156.14 90 bottom
CV75  -  [C_0402]  166.09 114.06 270 top
CV76  -  [C_0402]  165.2 114.06 270 top
CV77  -  [C_0603]  163.73 113.22 270 top
CV78  -  [C_0402]  165.2 115.84 270 top
CV79  -  [C_0402]  166.09 115.84 270 top
CV80  -  [C_0603]  163.73 115.64 270 top
CV81  -  [C_0402]  185.02 102.24 180 bottom
CV82  -  [C_0603]  161.7 105.35 90 bottom
CV83  -  [C_0402]  170.45 108.97 0 top
CV84  -  [C_0402]  170.45 109.86 0 top
CV85  -  [C_0402]  179.86 94.57 270 bottom
CV86  -  [C_0603]  161.7 104.33 270 bottom
CV87  -  [C_0402]  170.58 105.92 0 top
CV88  -  [C_0402]  170.58 106.81 0 top
CV89  -  [C_0402]  178.03 92.65 180 bottom
CV91  -  [C_0603]  158.52 107.57 180 bottom
CV92  -  [C_0402]  158.6 105.54 180 bottom
CV93  -  [C_0402]  158.6 106.49 180 bottom
CV94  -  [C_0402]  170.54 101.16 180 bottom
CV95  -  [C_0402]  171.4 101.16 0 bottom
CV97  -  [C_0805]  166.59 126.16 90 top
CV101  -  [C_0603]  182.21 93.73 90 bottom
CV102  -  [C_0603]  180.94 93.73 90 bottom
CV103  -  [C_0603]  188.18 94.81 270 bottom
CV108  -  [C_0402]  174.22 106.68 180 top
CV109  -  [C_0402]  174.6 109.16 180 top
CV110  -  [C_0603]  161.7 104.33 270 top
CV111  -  [C_0603]  182.27 100.21 180 bottom
CV112  -  [C_0402]  182.34 101.3 180 bottom
CV113  -  [C_0402]  182.34 102.19 180 bottom
CV114  -  [C_0402]  160.55 105.91 90 top
CV115  -  [C_0402]  159.6 105.91 90 top
CV116  -  [C_0603]  158.52 105.98 90 top
CV117  -  [C_0603]  185.95 100.28 0 bottom
CV118  -  [C_0402]  185.88 102.24 0 bottom
CV119  -  [C_0402]  185.88 101.35 0 bottom
CV120  -  [C_0603]  157.63 104.4 270 top
CV121  -  [C_0402]  159.61 104.43 270 top
CV122  -  [C_0402]  158.72 104.43 270 top
CV123  -  [C_0603]  158.65 101.22 270 top
CV124  -  [C_0402]  160.62 101.22 270 top
CV125  -  [C_0402]  159.73 101.22 270 top
CV126  -  [C_0402]  155.79 112.54 270 top
CV127  -  [C_0402]  156.68 112.54 270 top
CV128  -  [C_0402]  155.22 114.23 90 top
CV129  -  [C_0402]  156.17 114.23 90 top
CV130  -  [C_0402]  157.57 112.54 270 top
CV131  -  [C_0603]  154.65 113.1 270 top
CV132  -  [C_0402]  161.13 115.94 90 bottom
CV133  -  [C_0402]  162.02 115.94 90 bottom
CV134  -  [C_0603]  159.73 114.62 90 bottom
CV135  -  [C_B2]  160.34 157.43 0 top
CV136  -  [C_0603]  197.83 156.53 90 top
CV137  -  [C_0603]  203.55 144.79 90 bottom
CV138  -  [C_0603]  218.34 113.29 0 bottom
CV139  -  [C_0603]  218.53 121.17 0 top
CV140  -  [C_0603]  194.21 156.53 90 top
CV141  -  [C_0402]  191.35 156.33 90 top
CV142  -  [C_0402]  171.49 132.15 180 top
CV143  -  [C_0402]  170.54 129.29 180 top
CV144  -  [C_0402]  186.27 109.43 270 top
CV145  -  [C_0402]  190.45 156.3 90 top
CV146  -  [C_0402]  172.17 120.6 0 top
CV147  -  [C_0402]  172.37 123.71 0 top
CV148  -  [C_0402]  172.37 124.61 0 top
CV149  -  [C_0402]  171.73 127.53 270 top
CV150  -  [C_0402]  170.54 128.4 180 top
CV151  -  [C_0603]  170.65 127.45 270 top
CV152  -  [C_0402]  162.21 156.21 90 top
CV153  -  [C_0402]  171.49 133.04 180 top
CV154  -  [C_0402]  188.3 109.11 0 top
CV155  -  [C_0402]  188.38 113.29 180 top
CV156  -  [C_0402]  186.08 117.71 270 top
CV170  -  [C_0603]  171.03 96.73 270 bottom
CV171  -  [C_0402]  173.06 96.73 270 bottom
CV172  -  [C_0402]  172.18 96.73 270 bottom
CV173  -  [C_0402]  173.58 114.78 270 top
CV174  -  [C_0402]  172.68 114.78 270 top
CV187  -  [C_0603]  177.19 113.41 270 top
CV188  -  [C_0402]  176.19 113.48 180 top
CV189  -  [C_0402]  175.43 112.59 180 top
CV190  -  [C_0402]  175.28 114.82 0 top
CV193  -  [C_0402]  186.59 113.68 270 top
CV194  -  [C_0402]  185.95 114.99 90 top
CV195  -  [C_0402]  174.52 124.52 0 top
CV196  -  [C_0402]  174.52 123.63 0 top
CV197  -  [C_0603]  202.39 147.6 0 top
CV198  -  [C_0402]  202.89 146.45 0 top
CV199  -  [C_0402]  202.89 145.44 0 top
CV200  -  [C_0603]  190.78 95.82 0 bottom
CV201  -  [C_0402]  191.14 97.81 0 bottom
CV202  -  [C_0402]  191.14 96.92 0 bottom
CV203  -  [C_0402]  183.54 120.7 0 top
CV204  -  [C_0402]  184.25 122.83 90 top
CV205  -  [C_0402]  183.49 119.76 0 top
CV206  -  [C_0402]  183.49 125.93 90 top
CV207  -  [C_0402]  179.54 125.62 0 top
CV208  -  [C_0402]  183.51 121.59 0 top
CV209  -  [C_0402]  184.45 124.61 180 top
CV210  -  [C_0402]  179.57 126.51 0 top
CV211  -  [C_0402]  182.6 125.93 90 top
CV212  -  [C_0402]  181.33 125.55 90 top
CV213  -  [C_0603]  182.75 107.48 270 top
CV214  -  [C_0603]  181.54 107.48 270 top
CV215  -  [C_0603]  194.59 95.82 180 bottom
CV216  -  [C_0402]  194.28 96.92 180 bottom
CV217  -  [C_0402]  194.28 97.81 180 bottom
CV218  -  [C_0402]  194.35 94.3 180 top
CV219  -  [C_0402]  191.53 92.46 0 top
CV220  -  [C_0402]  161.11 128.85 0 bottom
CV221  -  [C_0402]  161.11 133.35 0 bottom
CV222  -  [C_0402]  209.07 99.05 90 top
CV223  -  [C_0402]  196.2 103.27 90 bottom
CV224  -  [C_0402]  196.19 105.95 270 bottom
CV280  -  [C_0402]  218.52 138.95 0 bottom
CV281  -  [C_0402]  218.52 138.06 0 bottom
CV283  -  [C_0402]  218.52 136.6 0 bottom
CV284  -  [C_0402]  218.52 135.71 0 bottom
CV285  -  [C_0402]  218.52 134.44 0 bottom
CV286  -  [C_0402]  218.52 133.55 0 bottom
CV287  -  [C_0402]  218.52 131.77 0 bottom
CV288  -  [C_0402]  218.52 130.88 0 bottom
CV290  -  [C_0402]  218.52 129.99 0 bottom
CV291  -  [C_0402]  219.03 131.07 0 top
CV292  -  [C_0402]  219.03 132.85 0 top
CV293  -  [C_0402]  219.03 129.3 0 top
CV294  -  [C_0402]  219.03 128.41 0 top
CV295  -  [C_0402]  218.46 123.75 0 bottom
CV296  -  [C_0402]  218.46 122.86 0 bottom
CV297  -  [C_0402]  218.52 129.11 0 bottom
CV298  -  [C_0402]  218.33 113.87 0 top
CV299  -  [C_0402]  218.33 114.75 0 top
CV301  -  [C_0402]  218.33 109.29 0 bottom
CV302  -  [C_0402]  218.33 110.18 0 bottom
CV303  -  [C_0402]  218.39 112.15 0 bottom
CV304  -  [C_0402]  218.33 104.59 0 bottom
CV305  -  [C_0402]  218.71 105.61 0 top
CV306  -  [C_0402]  218.77 107.83 0 top
CV307  -  [C_0402]  218.77 110.18 0 top
CV308  -  [C_0402]  218.33 111.58 0 top
CV310  -  [C_0402]  218.39 115.64 0 top
CV311  -  [C_0402]  218.39 116.53 0 top
CV312  -  [C_0402]  218.39 111.26 0 bottom
CV313  -  [C_0402]  218.33 107.83 0 bottom
CV315  -  [C_0402]  218.33 106.94 0 bottom
CV316  -  [C_0402]  218.33 105.48 0 bottom
CV318  -  [C_0402]  218.71 104.72 0 top
CV319  -  [C_0402]  218.77 109.29 0 top
CV322  -  [C_0603]  183.99 117.88 270 top
CV323  -  [C_0603]  180.32 107.46 270 top
CV324  -  [C_0603]  177.77 125.43 90 top
CV325  -  [C_0402]  180.21 111.46 180 top
CV326  -  [C_0402]  161.82 109.68 270 bottom
CV327  -  [C_D2]  161.79 129.8 180 top
CV328  -  [C_0402]  170.78 138.19 90 top
CV329  -  [C_0402]  167.29 98.07 90 top
CV330  -  [C_0402]  158.13 148.54 0 top
CV331  -  [C_0402]  160.81 110.51 270 top
CV332  -  [C_0402]  180.62 156.27 90 top
CV333  -  [C_0402]  159.41 111.62 90 top
CV335  -  [C_0402]  155.92 110.19 270 top
CV349  -  [C_0402]  188.24 139.04 270 top
CV350  -  [C_0402]  190.02 138.12 90 top
CV351  -  [C_0402]  181.51 156.14 90 bottom
CV352  -  [C_0402]  183.29 157.06 270 bottom
CV353  -  [C_0402]  188.24 139.04 270 bottom
CV354  -  [C_0402]  190.02 138.12 90 bottom
CV355  -  [C_0402]  201.39 155.06 90 bottom
CV356  -  [C_0402]  199.61 155.98 270 bottom
CV368  -  [C_0402]  184.18 156.27 90 top
CV369  -  [C_0402]  185.26 156.14 90 bottom
CV370  -  [C_0402]  192.24 156.33 90 top
CV371  -  [C_0402]  183.29 156.27 90 top
CV372  -  [C_0402]  171.42 156.21 90 bottom
CV373  -  [C_0402]  174.59 156.53 90 top
CV374  -  [C_0402]  169.07 156.21 90 bottom
CV375  -  [C_0402]  168.18 156.21 90 bottom
CV376  -  [C_0402]  193.96 156.14 90 bottom
CV377  -  [C_0402]  192.5 156.14 90 bottom
CV378  -  [C_0402]  170.53 156.21 90 bottom
CV379  -  [C_0402]  189.58 156.27 90 top
CV380  -  [C_0402]  172.81 156.53 90 bottom
CV381  -  [C_0402]  191.61 156.14 90 bottom
CV382  -  [C_0402]  190.21 156.14 90 bottom
CV383  -  [C_0402]  187.8 156.27 90 top
CV384  -  [C_0402]  218.52 132.66 0 bottom
CV385  -  [C_0402]  219.03 130.19 0 top
CV386  -  [C_0402]  218.52 128.22 0 bottom
CV387  -  [C_0402]  159.05 152.98 180 top
CV388  -  [C_0402]  170.78 138.19 90 bottom
CV389  -  [C_0402]  200.96 157.93 180 top
CV390  -  [C_0402]  200.04 156.16 0 top
CV391  -  [C_0402]  218.77 106.94 0 top
CV392  -  [C_0402]  218.33 112.47 0 top
CV393  -  [C_0402]  158.13 151.2 0 top
CV394  -  [C_0402]  176.18 157.3 270 bottom
CV395  -  [C_0402]  177.96 156.39 90 bottom
CV396  -  [C_0402]  176.18 157.3 270 top
CV397  -  [C_0402]  168.11 139.1 270 bottom
CV398  -  [C_0402]  177.96 156.39 90 top
CV399  -  [C_0402]  169 139.1 270 top
CV400  -  [C_0402]  159.03 146.77 270 top
CV401  -  [C_0402]  182.4 156.27 90 top
CX1  -  [C_0402]  216.7 173.75 180 top
CX2  -  [C_0402]  213.96 167.73 270 bottom
CX3  -  [C_0805]  215.01 167.9 0 bottom
CX4  -  [C_0402]  219.87 176.27 90 top
CX5  -  [C_0603]  224.5 175.71 90 top
CX6  -  [C_0402]  27.27 96.57 90 top
CX7  -  [C_0805]  216.21 172.41 180 top
CX8  -  [C_0805]  216.37 171.1 270 bottom
CX9  -  [C_0402]  217.83 166.84 270 top
CX10  -  [C_0402]  213.57 161.05 0 bottom
CX11  -  [C_0402]  213.2 170.37 90 bottom
CX31  -  [C_0402]  199.04 170.9 180 bottom
CX32  -  [C_0402]  199.6 167.6 180 top
CX33  -  [C_0402]  199.04 170.03 180 bottom
CX34  -  [C_0402]  203.99 165.31 270 top
CX35  -  [C_0603]  198.09 168.98 180 bottom
CX36  -  [C_0805]  206.82 164.86 0 top
CX37  -  [C_0402]  204.88 175.58 90 top
CX38  -  [C_0402]  196.74 169.2 0 top
CX39  -  [C_0402]  196.74 168.31 0 top
CX40  -  [C_0402]  204.64 163.01 180 top
CX41  -  [C_0402]  205.77 165.31 270 top
CX42  -  [C_0402]  198.52 170.38 0 top
CX43  -  [C_0402]  198.52 171.27 0 top
CX44  -  [C_0402]  198.52 172.16 0 top
CX45  -  [C_0603]  204.56 161.81 180 top
CX46  -  [C_0402]  198.52 169.49 0 top
CX47  -  [C_0402]  199.33 161.78 180 top
CX48  -  [C_0805]  198.92 163.45 90 top
DA8  -  [BAT54C-7-F_SOT23-3]  38.13 25.32 0 top
DA10  -  [AZ5125-02SPR7G_SOT23-3]  18.13 11.19 90 top
DA12  -  [AZ5125-02SPR7G_SOT23-3]  16.44 14.46 0 top
DC1  -  [BAT54CW_SOT323-3]  203.31 13.16 180 bottom
DE1  -  [L03ESDL5V0CG3-2_SOT-523-3]  171.4 44.32 0 top
DE2  -  [BAT1000-7-F_SOT23-3]  10.74 117.28 90 bottom
DE3  -  [PESD5V0U2BT_SOT23-3]  11.54 102.46 90 top
DE4  -  [PESD5V0U2BT_SOT23-3]  11.57 106.65 90 top
DE5  -  [PESD5V0U2BT_SOT23-3]  11.55 110.81 90 top
DH1  -  [RB751V-40_SOD323-2]  144.25 117.62 270 bottom
DI1  -  [IP4292CZ10-TBR_XSON10_2P5X1]  16.69 59.91 90 bottom
DI2  -  [L30ESDL5V0C3-2_SOT23-3]  17.09 57.03 90 bottom
DI4  -  [IP4292CZ10-TBR_XSON10_2P5X1]  17.51 46.76 90 bottom
DI5  -  [L30ESDL5V0C3-2_SOT23-3]  16.58 44.27 90 bottom
DI7  -  [L30ESDL5V0C3-2_SOT23-3]  15.04 27.89 90 bottom
DX1  -  [RB751V-40_SOD323-2]  219.42 165.64 270 bottom
FD1  -  [FIDUCIAL_C40M80]  226.98 161.94 180 bottom
FD2  -  [FIDUCIAL_C40M80]  16.35 9.6 180 bottom
FD3  -  [FIDUCIAL_C40M80]  39.46 14.04 0 top
FD4  -  [FIDUCIAL_C40M80]  227.42 177.37 0 top
H2  -  [H_2P8]  109.2 13.4 0 top
H4  -  [H_2P8]  19.2 71.9 0 top
H5  -  [H_2P8]  21.9 4.9 0 top
H6  -  [H_3P3]  204.1 94.4 0 top
H7  -  [H_3P3]  153.3 144.5 0 top
H8  -  [H_2P8]  225.2 81.4 0 top
H9  -  [H_2P8]  225.2 168.4 0 top
H10  -  [H_3P3]  26.92 119.1 0 top
H11  -  [H_2P8]  164.2 185.4 0 top
H12  -  [H_2P8]  31.2 109.4 0 top
H16  -  [H_2P8]  127.6 154.8 0 top
H17  -  [H_2P8]  225.2 4.9 0 top
H18  -  [H_3P3]  19.2 38.1 0 top
H31  -  [H_3P7]  80.8 129.06 0 top
H32  -  [H_3P7]  141.2 103.66 0 top
H33  -  [H_3P7]  141.2 129.06 0 top
H34  -  [H_3P7]  80.8 103.66 0 top
H35  -  [H_3P7X3P2N]  195.55 187.5 0 top
J9  -  [JUMP_43X39]  185.84 86.5 180 bottom
J510  -  [JUMP_43X79]  100.59 31.57 180 bottom
J511  -  [JUMP_43X79]  92.63 31.57 0 bottom
J513  -  [JUMP_43X79]  139.79 27.23 270 top
JCRT1  -  [C-K_80443B-5K1-152_15P-T]  5.4 103.42 270 bottom
JDB  -  [JESS_UCNR2210M008-0_8P]  210.6 45.7 270 top
JDIMM1  -  [LCN_DAN06-K4406-0102_204P]  41.8 71.4 0 bottom
JDIMM2  -  [LCN_DAN06-K4406-0102_204P]  120.35 71.44 0 bottom
JFAN  -  [ACES_85204-0300N_3P]  48.69 108.61 0 bottom
JHDD  -  [SANTA_193202-1_22P]  227.22 37.39 270 bottom
JHP  -  [SINGA_2SJ3080-000111F_6P-T]  11.75 8.09 270 bottom
JKB  -  [HB_A823020-SBHR21_30P]  228.6 159.82 270 top
JLAN  -  [SANTA_130456-311_8P]  15 79.23 90 bottom
JLVDS  -  [STARC_107K40-000001-G2_40P]  204.45 173.45 0 bottom
JMINI  -  [CONCR_525B01BE17A_52P]  93.3 150.67 0 bottom
JODD  -  [SANTA_202801-1_13P]  227.05 98.22 270 bottom
JP3  -  [JUMP_43X39]  45.17 85.29 0 bottom
JP7  -  [JUMP_43X79]  220.21 115.83 0 bottom
JP8  -  [JUMP_43X39]  182.13 91.57 0 bottom
JP9  -  [JUMP_43X39]  214.01 151.26 0 bottom
JP12  -  [JUMP_43X39]  200.49 12.46 0 bottom
JP13  -  [JUMP_43X79]  219.31 60.09 270 top
JPWR  -  [HB_A090420-SAHR21_4P]  45.34 95.4 180 top
JREAD  -  [T-SOL_143-2300302602_22P_RV]  191.48 29.92 180 bottom
JRTC  -  [LOTES_AAA-BAT-054-K01_2P]  210.2 9.4 270 bottom
JSPK  -  [E-T_3703-Q04N-11R_4P]  69.77 21.88 90 top
JTOUCH  -  [ACES_88460-00601-P01_6P]  23.71 96.89 180 top
JTP  -  [PS_HPF10052-06M000R_6P]  66.35 110.35 0 top
JUSB1  -  [ACON_TARA4-9K1311_9P]  12.69 67.1 90 bottom
JUSB2  -  [ACON_TARA4-9K1311_9P]  12.69 49.5 90 bottom
JUSB3  -  [ACON_UARBG-4K1926_4P]  10.32 31.9 90 bottom
JXDP1  -  [SAMTE_BSH-030-01-L-D-A_60P]  73.2 93.43 180 bottom
L1  -  [MURAT_LQM2MPN2R2NG0L_2P]  119.54 137.4 270 bottom
L2  -  [MURAT_LQM2MPN2R2NG0L_2P]  121.02 141.62 0 bottom
L3  -  [MURAT_LQM2MPN2R2NG0L_2P]  123.88 138.88 0 bottom
L4  -  [MURAT_LQM2MPN2R2NG0L_2P]  121.76 139.88 270 bottom
L5  -  [MURAT_LQM2MPN2R2NG0L_2P]  117.31 137.4 270 bottom
L6  -  [MURAT_BLM18BD102SN1D_L0603_2P]  11.36 99.5 180 bottom
L8  -  [MURAT_BLM18BD102SN1D_L0603_2P]  11.36 103.12 180 bottom
L9  -  [MURAT_BLM18BD102SN1D_L0603_2P]  11.3 108.33 180 bottom
L10  -  [R_0603]  24.03 113.41 270 top
L11  -  [R_0603]  21.68 113.41 270 top
L12  -  [R_0603]  20.35 113.41 270 top
LA1  -  [MURAT_BLM15BB221SN1D_2P]  32.29 19.12 0 top
LA3  -  [R_0603]  64.04 20.71 0 top
LA4  -  [R_0603]  64.04 21.92 0 top
LA5  -  [R_0603]  63.08 23.7 0 top
LA6  -  [R_0603]  63.08 24.9 0 top
LA7  -  [KC_FBMA-L10-160808-800LMT_2P]  15.59 20.28 90 top
LA8  -  [KC_FBMA-L10-160808-800LMT_2P]  23.41 11.1 0 top
LA9  -  [KC_FBMA-L10-160808-800LMT_2P]  23.41 12.62 0 top
LA10  -  [KC_FBMA-L10-160808-800LMT_2P]  17.11 20.28 90 top
LE1  -  [KC_FBMA-L11-160808-800LMT_2P]  199.62 35.7 0 top
LE2  -  [KC_FBMA-L11-160808-800LMT_2P]  194.21 55.5 270 top
LED1  -  [LED_12-21C-T3D-CM2P1B18X-2C_3P]  31.81 10.74 0 top
LED2  -  [LED_12-21C-T3D-CM2P1B18X-2C_3P]  40.8 10.74 0 top
LED3  -  [LED_HT-210UD5-BP5_3P]  46.9 10.74 0 top
LED4  -  [LED_12-21C-T3D-CM2P1B18X-2C_3P]  58.81 10.7 0 top
LI1  -  [MURAT_DLW21SN670HQ2L_4P]  21.26 59.49 180 bottom
LI2  -  [KC_WCM-2012HS-900T_4P]  22.85 57.43 180 bottom
LI3  -  [MURAT_DLW21SN670HQ2L_4P]  21.26 61.4 180 bottom
LI4  -  [MURAT_DLW21SN670HQ2L_4P]  22.34 46.16 180 bottom
LI5  -  [KC_WCM-2012HS-900T_4P]  22.85 44.61 180 bottom
LI6  -  [MURAT_DLW21SN670HQ2L_4P]  22.34 47.93 180 bottom
LI7  -  [KC_WCM-2012HS-900T_4P]  20.75 27.91 180 bottom
LI10  -  [KC_WCM-2012HS-900T_4P]  205.68 49.11 0 top
LR2  -  [KC_WCM-2012HS-900T_4P]  171.95 33.05 180 bottom
LV12  -  [R_0402]  162.59 112.64 270 top
LV13  -  [R_0402]  162.59 115.14 270 top
LV14  -  [R_0402]  160.55 106.19 270 bottom
LV15  -  [R_0402]  160.55 103.84 270 bottom
LV16  -  [R_0402]  159.54 105.27 90 bottom
LV17  -  [CHENG_MBK1608121YZF_2P]  153.38 111.28 90 top
LV18  -  [CHENG_MBK1608121YZF_2P]  156.77 114.75 0 bottom
LV19  -  [R_0402]  169.05 96.73 0 bottom
LV20  -  [R_0402]  184.1 99.51 0 bottom
LV21  -  [KC_FBMA-L11-160808-800LMT_2P]  203.72 148.99 180 top
LV22  -  [R_0402]  191.75 94.75 180 bottom
LV23  -  [KC_FBMA-L11-160808-800LMT_2P]  194.21 92.92 90 bottom
LV25  -  [R_0402]  180.95 113.1 180 top
LV26  -  [R_0402]  182.28 114.68 180 top
LX1  -  [KC_FBMA-L11-201209-221LMA30_2P]  214.6 169.43 90 bottom
LX6  -  [KC_WCM-2012HS-900T_4P]  219.02 165.34 90 top
LX7  -  [KC_FBMA-L11-201209-221LMA30_2P]  205.96 162.89 270 top
LX8  -  [KC_FBMA-L11-201209-221LMA30_2P]  197.49 167.19 0 bottom
LX9  -  [CYNTE_PG031B-4R7MS_2P]  200.48 164.09 0 top
ME1  -  [SHORTPADS]  115.46 40.16 180 bottom
NOREF  -  []  225.2 4.9 0 top
NOREF#2  -  []  80.8 103.66 0 top
NOREF#3  -  []  204.1 94.4 0 top
NOREF#4  -  []  32.86 216.61 0 top
NOREF#5  -  []  141.2 103.65 0 top
NOREF#6  -  []  31.2 109.4 0 top
NOREF#7  -  []  225.2 81.4 0 top
NOREF#8  -  []  19.2 38.1 0 top
NOREF#9  -  []  26.92 119.1 0 top
NOREF#10  -  []  108.36 -20.5 0 top
NOREF#11  -  []  50.45 30.36 0 top
NOREF#12  -  []  21.9 4.9 0 top
NOREF#13  -  []  123.09 42 0 top
NOREF#14  -  []  19.2 71.9 0 top
NOREF#15  -  []  109.2 13.4 0 top
NOREF#16  -  []  127.96 79.22 0 top
NOREF#17  -  []  164.2 185.4 0 top
NOREF#18  -  []  104.11 81.61 0 top
NOREF#19  -  []  127.6 154.8 0 top
NOREF#20  -  []  80.8 129.06 0 top
NOREF#21  -  []  74.32 49.5 0 top
NOREF#22  -  []  153.3 144.5 0 top
NOREF#23  -  []  30.83 -164.65 0 top
NOREF#24  -  []  141.2 129.05 0 top
NOREF#25  -  []  225.2 168.4 0 top
NOREF#26  -  []  158.78 39.19 180 bottom
NOREF#27  -  []  63.64 -188.13 180 bottom
NOREF#28  -  []  69.88 31.6 180 bottom
NOREF#29  -  []  140.94 37.03 180 bottom
PBATT  -  [SUYIN_200028MR009G502ZL_9P]  139.52 188.7 0 bottom
PC1  -  [C_0402]  139.79 179.89 90 bottom
PC2  -  [C_0402]  140.68 179.89 90 bottom
PC3  -  [C_0402]  138.71 168.49 270 top
PC4  -  [C_0402]  137.82 168.49 270 top
PC5  -  [C_0402]  129.24 172.01 180 top
PC7  -  [C_0402]  158.07 181.05 0 bottom
PC8  -  [C_0402]  158.07 182.19 0 bottom
PC13  -  [C_0402]  130.85 180.79 180 top
PC14  -  [C_0402]  132.11 164.49 270 top
PC15  -  [C_0402]  127.54 163.57 90 top
PC16  -  [C_0402]  127.47 167.32 90 top
PC100  -  [C_0603]  119 13.19 90 top
PC101  -  [C_APXK6R3ARA221MF451]  137.06 18.26 180 bottom
PC102  -  [C_0402]  129.82 12.06 90 top
PC103  -  [C_0603]  132.68 21.25 180 top
PC104  -  [C_0402]  131.53 15.79 0 top
PC105  -  [C_0603]  128.54 18.07 180 bottom
PC106  -  [C_0603]  127.58 20.18 180 bottom
PC107  -  [C_APXK6R3ARA221MF451]  118.32 18.43 0 bottom
PC108  -  [C_0402]  126.67 12.99 270 bottom
PC109  -  [C_0603]  127.82 12.92 270 top
PC110  -  [C_0402]  123.21 16.39 0 top
PC111  -  [C_0603]  121.63 21.46 0 top
PC112  -  [C_0805]  128.58 25.41 270 bottom
PC113  -  [C_0402]  126.33 25.55 270 top
PC114  -  [C_0402]  127.23 25.58 270 top
PC115  -  [C_0805]  128.58 25.41 270 top
PC200  -  [C_0603]  154.91 21.68 0 bottom
PC201  -  [C_0402]  163.8 14.95 270 bottom
PC202  -  [C_0402]  162.01 24.33 0 bottom
PC203  -  [C_0402]  162.01 26.11 0 bottom
PC204  -  [C_0603]  159.67 20.03 90 bottom
PC205  -  [C_0805]  154.91 27.14 270 bottom
PC206  -  [C_0805]  159.86 16.36 270 bottom
PC207  -  [C_0402]  156.42 11.19 0 bottom
PC208  -  [C_0402]  162.91 14.95 270 bottom
PC209  -  [C_0603]  160.88 21.42 270 bottom
PC210  -  [C_0402]  159.67 28.22 90 bottom
PC211  -  [C_0805]  156.88 28.6 0 bottom
PC212  -  [C_0805]  161.57 16.36 270 bottom
PC213  -  [C_APXK6R3ARA221MF451]  146.72 22.44 0 bottom
PC300  -  [C_0402]  148.17 150.12 0 bottom
PC301  -  [C_0603]  139.23 150.5 90 bottom
PC302  -  [C_0603]  148.43 158.05 180 bottom
PC303  -  [C_0402]  143.42 157.28 90 bottom
PC304  -  [C_0402]  142.53 157.28 90 bottom
PC305  -  [C_0805]  141.32 155.16 270 bottom
PC306  -  [C_0805]  139.61 155.16 270 bottom
PC307  -  [C_0402]  147.74 153.72 90 bottom
PC308  -  [C_0805]  141.7 142.35 90 top
PC309  -  [C_0805]  143.41 142.35 90 top
PC310  -  [C_0805]  146.84 142.35 90 top
PC311  -  [C_0805]  145.13 142.35 90 top
PC312  -  [C_0603]  147.04 155.64 0 bottom
PC313  -  [C_0603]  144.5 157.48 0 bottom
PC400  -  [C_0805]  112.85 29.59 270 bottom
PC401  -  [C_0402]  107.44 25.89 0 bottom
PC402  -  [C_0805]  111.14 29.59 270 bottom
PC403  -  [C_0402]  111.9 26.85 270 bottom
PC404  -  [C_0402]  113.68 24.69 270 bottom
PC405  -  [C_0805]  107.9 23.13 90 bottom
PC501  -  [C_0402]  117.61 138.97 180 bottom
PC502  -  [C_0402]  114.24 145.06 270 bottom
PC503  -  [C_0603]  82.9 135.39 90 bottom
PC504  -  [C_0402]  86.95 136.34 0 top
PC505  -  [C_0603]  90.14 131.66 0 bottom
PC506  -  [C_0402]  88.74 136.29 270 top
PC507  -  [C_0402]  89.95 135.38 90 top
PC508  -  [C_0603]  89.69 142.69 270 bottom
PC509  -  [C_0402]  90.26 139.85 270 top
PC510  -  [C_0402]  93.89 139.08 180 bottom
PC511  -  [C_0402]  93.89 139.96 180 bottom
PC512  -  [C_0402]  86.95 135.46 0 top
PC513  -  [C_0402]  92.66 134.38 0 bottom
PC514  -  [C_0402]  91.79 132.66 90 bottom
PC515  -  [C_EEEFZ1E101P]  129.63 143.23 270 bottom
PC516  -  [C_EEEFZ1E101P]  136.74 143.16 270 bottom
PC517  -  [C_0805]  117.31 143.24 90 top
PC518  -  [C_0805]  117.31 143.24 90 bottom
PC519  -  [C_0402]  115.13 144.14 90 bottom
PC520  -  [C_0402]  107.22 142.81 90 top
